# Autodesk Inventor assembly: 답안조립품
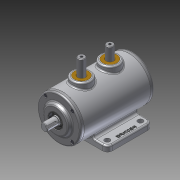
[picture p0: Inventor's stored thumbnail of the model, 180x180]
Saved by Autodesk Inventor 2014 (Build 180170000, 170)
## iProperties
Created: 2014-12
Part Number: 답안조립품
Document SubType Name: Assembly
Designer: Owner
Author: Owner
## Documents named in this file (10)
- C:\Users\Owner\Desktop\441223V1012\답안조립품.iam
- C:\Users\Owner\Desktop\441223V1012\본체.ipt
- C:\Users\Owner\Desktop\441223V1012\M4-소켓머리.ipt
- C:\Users\Owner\Desktop\441223V1012\뒷커버.ipt
- C:\Users\Owner\Desktop\441223V1012\베어링 6203.ipt
- C:\Users\Owner\Desktop\441223V1012\부시.ipt
- C:\Users\Owner\Desktop\441223V1012\슬라이더.ipt
- C:\Users\Owner\Desktop\441223V1012\앞커버.ipt
- C:\Users\Owner\Desktop\441223V1012\오일실.ipt
- C:\Users\Owner\Desktop\441223V1012\축.ipt
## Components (11 placed, 3 different names)
1. 7-베어링 6203:1
2. 8-오일실:1
3. 7-베어링 6203:2
4. 9-M4-소켓머리:10
5. 9-M4-소켓머리:11
6. 9-M4-소켓머리:12
7. 9-M4-소켓머리:13
8. 9-M4-소켓머리:14
9. 9-M4-소켓머리:15
10. 9-M4-소켓머리:16
11. 9-M4-소켓머리:17
